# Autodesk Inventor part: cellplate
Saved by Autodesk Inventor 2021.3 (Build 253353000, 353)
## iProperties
Created: 2023-07
Part Number: cellplate
Material: Generic
Document SubType Name: Modeling
Designer: AdminForWorker
Density: 1 g/cm^3
Appearance: Default
Title: cellplate
Author: AdminForWorker
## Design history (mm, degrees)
feature "cellplate"
body "Solid1"
